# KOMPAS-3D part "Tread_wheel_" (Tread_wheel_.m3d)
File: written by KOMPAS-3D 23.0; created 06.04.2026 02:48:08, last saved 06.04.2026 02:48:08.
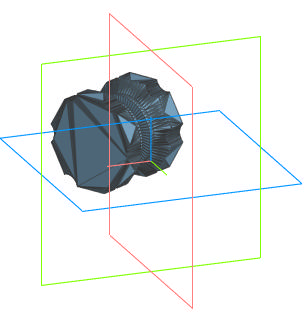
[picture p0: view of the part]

Document properties: Автор: Стас; Полное имя файла: C:\Users\Стас\Desktop\Tank Tread - 332816\files\Tread_wheel_.m3d

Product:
- Part/product: Tread_wheel_

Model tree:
1. Полигональный объект:1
